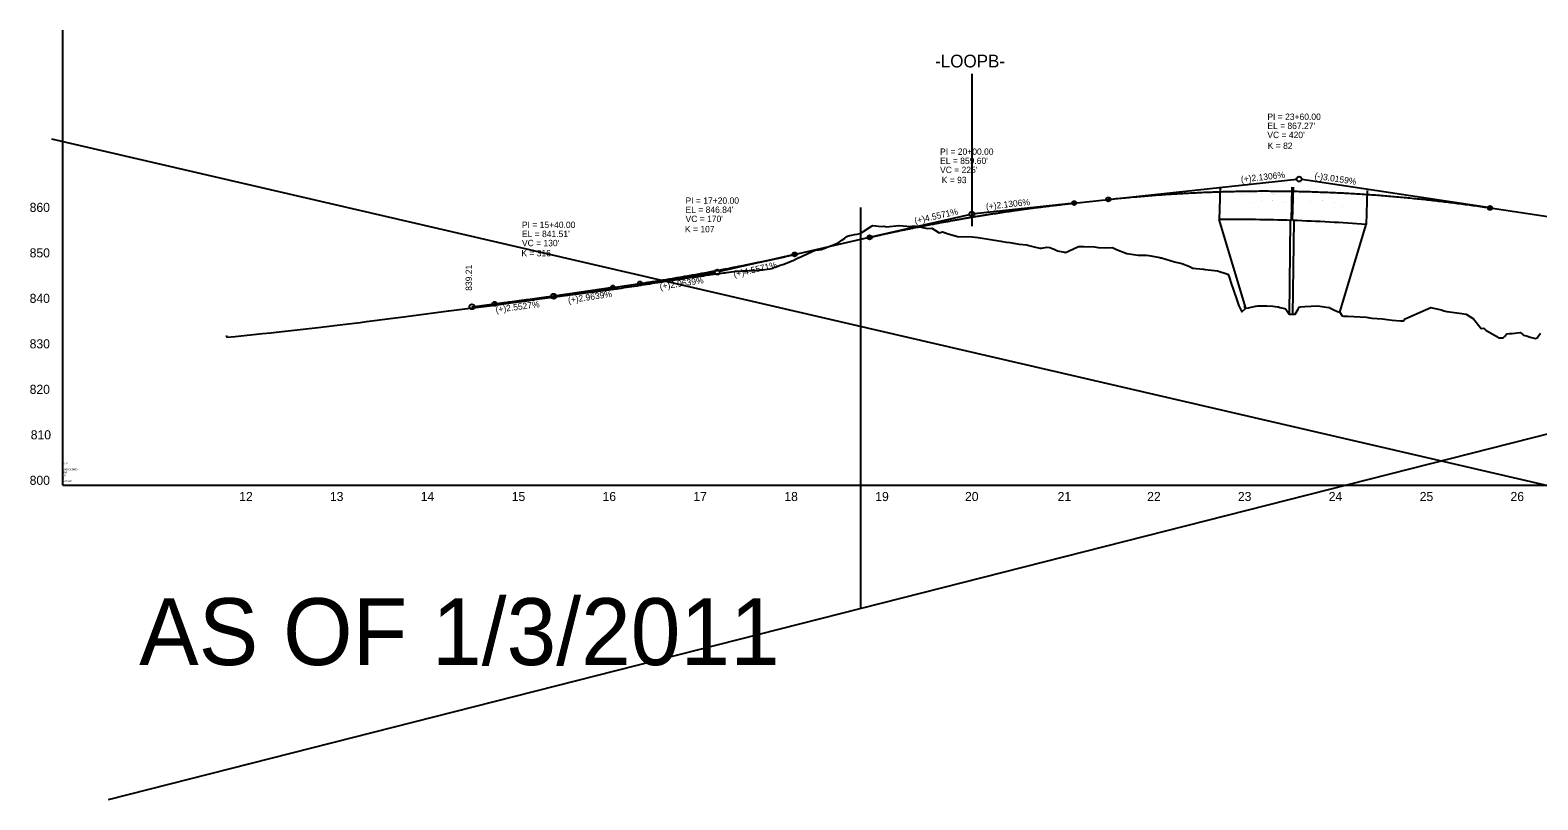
# Model space of a CAD drawing. Extents: x 570622 to 580296, y -55533 to -48575.
# Drawn here: x 573623 to 575281, y -49421 to -48575 of the extents above; entities that cross this region are included whole.
import ezdxf

# ---------------------------------------------------------------- set-up
doc = ezdxf.new("R2010")
doc.units = 0
for name, color, linetype in [('Default', 7, 'Continuous'), ('Exist Profile Cell', 7, 'Continuous'), ('Exist Vertical Profile Ground Line', 7, 'Continuous'), ('Exist Vertical Profile Horizontal Axis Label Major', 7, 'Continuous'), ('Exist Vertical Profile Vertical Axis Label', 7, 'Continuous'), ('Prop Vertical Profile Curve Label', 7, 'Continuous'), ('Prop Vertical Profile Grade', 7, 'Continuous'), ('Prop Vertical Profile Grade Label', 7, 'Continuous'), ('Prop VPI Label', 7, 'Continuous')]:
    doc.layers.add(name, color=color, linetype=linetype)

msp = doc.modelspace()

# ---------------------------------------------------------------- linework, layer by layer
at = {"layer": 'Default'}
for p, q in [((574658.6, -48623.1), (574658.6, -48790.2)), ((574931.8, -48748.4), (574930.7, -48783.1)), ((574955.7, -48754.4), (574955.7, -48754.4)), ((574957.2, -48756), (574957.2, -48756)), ((574957.2, -48756), (574957.2, -48756)), ((574963.9, -48752.7), (574963.9, -48752.7)), ((574965.4, -48754.3), (574965.4, -48754.3)), ((574965.4, -48754.3), (574965.4, -48754.3)), ((574975.6, -48752.4), (574975.6, -48752.4)), ((574977.1, -48754), (574977.1, -48754)), ((574977.2, -48754), (574977.2, -48754)), ((574987.3, -48753.5), (574987.3, -48753.5)), ((574988.8, -48755.1), (574988.8, -48755.1)), ((574988.8, -48755.1), (574988.8, -48755.1)), ((574989.9, -48754.3), (574989.9, -48754.3)), ((574991.4, -48755.9), (574991.4, -48755.9)), ((574991.4, -48755.9), (574991.4, -48755.9)), ((575010.1, -48784), (575010.9, -48747.5)), ((575011.4, -48784.1), (575012.3, -48747.5)), ((575017.7, -48752.8), (575017.7, -48752.8)), ((575019.1, -48754.5), (575019.1, -48754.5)), ((575019.1, -48754.5), (575019.1, -48754.5)), ((575030.9, -48752.1), (575030.9, -48752.1)), ((575031.7, -48752.5), (575031.7, -48752.5)), ((575032.8, -48753.7), (575032.8, -48753.7)), ((575044.2, -48754.1), (575044.2, -48754.1)), ((575045.7, -48755.8), (575045.7, -48755.8)), ((575045.7, -48755.8), (575045.7, -48755.8)), ((575052, -48758.6), (575052, -48758.6)), ((575054, -48760.2), (575054, -48760.2)), ((575054, -48760.2), (575054, -48760.2)), ((575093.4, -48751.1), (575092.2, -48788.4)), ((574536.6, -49210), (574536.6, -48769.9)), ((574968.9, -48764.8), (574968.9, -48764.8)), ((574968.9, -48764.8), (574968.9, -48764.8)), ((574977.3, -48762.7), (574977.3, -48762.7)), ((574977.3, -48762.7), (574977.3, -48762.7)), ((574989, -48762.2), (574989, -48762.2)), ((574989.1, -48762.2), (574989.1, -48762.2)), ((575000.7, -48763.3), (575000.7, -48763.3)), ((575000.7, -48763.3), (575000.7, -48763.3)), ((575003.4, -48764.1), (575003.4, -48764.1)), ((575003.4, -48764.1), (575003.4, -48764.1)), ((575031, -48762.9), (575031, -48762.9)), ((575031, -48762.9), (575031, -48762.9)), ((575044.3, -48762.2), (575044.3, -48762.2)), ((575044.6, -48762.2), (575044.6, -48762.2)), ((575057.6, -48764.1), (575057.6, -48764.1)), ((575057.6, -48764.1), (575057.6, -48764.1)), ((575066.1, -48768.4), (575066.1, -48768.4)), ((575066.1, -48768.4), (575066.1, -48768.4)), ((574959.9, -48880.6), (574930.7, -48783.1)), ((575008, -48887.7), (575009.2, -48784.1)), ((575011.8, -48887.7), (575013, -48784.1)), ((575063.3, -48884.9), (575092.2, -48788.4)), ((574958.9, -48880.6), (574958.9, -48877.3)), ((574959.9, -48880.6), (574958.9, -48880.6))]:
    msp.add_line(p, q, dxfattribs=at)
for start, end in [(88.1608, 90.5075), (85.7299, 88.1202)]:
    msp.add_arc((574947.9, -50721.6), 1938.5, start, end, dxfattribs=at)
at = {"layer": 'Exist Profile Cell'}
for p, q in [((573658.6, -49075), (573658.6, -48575)), ((576607.2, -48684.9), (573708.6, -49420.9)), ((573646, -48694.4), (576748.4, -49412.6)), ((573658.6, -49075), (576254.8, -49075)), ((573658.6, -49075), (573658.6, -49075))]:
    msp.add_line(p, q, dxfattribs=at)
at = {"layer": 'Exist Vertical Profile Ground Line'}
for points in [[(574354.9, -48846), (574356.9, -48845.7), (574357.7, -48845.6), (574360.5, -48845.2), (574363.3, -48844.8), (574366.1, -48844.3), (574368.9, -48843.9), (574369.5, -48843.9), (574371.8, -48843.5), (574374.6, -48843.1), (574377.4, -48842.7), (574377.9, -48842.6), (574380.2, -48842.3), (574383, -48842), (574385.8, -48841.6), (574387.3, -48841.5), (574388.7, -48841.3), (574391.5, -48840.9), (574393.9, -48840.6), (574394.3, -48840.5), (574397.1, -48840.1), (574398.8, -48839.9), (574399.9, -48839.8), (574402.8, -48839.7), (574405.6, -48839.6), (574408.4, -48839.5), (574411.2, -48839.3), (574414, -48839.2), (574416.8, -48839.2), (574419.7, -48839.1), (574420, -48839.1), (574422.5, -48838.8), (574425.3, -48838.5), (574428.1, -48838.2), (574430.9, -48837.9), (574433.7, -48837.7), (574436.7, -48837.4), (574439.9, -48836.4), (574440.2, -48836.2), (574440.9, -48835.9), (574442.2, -48835.4), (574445, -48834.4), (574447.8, -48833.4), (574450.6, -48832.4), (574453.5, -48831.3), (574456.3, -48830.2), (574459.1, -48829.2), (574460.6, -48828.6), (574461.9, -48828), (574464.7, -48826.7), (574467.5, -48825.3), (574470.4, -48824), (574471.8, -48823.3), (574473.2, -48822.7), (574476, -48821.4), (574478.8, -48820.1), (574481.6, -48818.8), (574484.4, -48817.5), (574486.5, -48816.6), (574487.3, -48816.5), (574490.1, -48816.4), (574492.9, -48816.1), (574495.7, -48815), (574498.5, -48813.9), (574501.3, -48812.8), (574504.2, -48811.7), (574504.6, -48811.5), (574507, -48810.5), (574509.8, -48809.4), (574511.2, -48808.9), (574512.6, -48807.9), (574515.4, -48805.8), (574518.3, -48803.8), (574521.1, -48801.8), (574521.7, -48801.3), (574522.8, -48800.9), (574523.9, -48800.7), (574526.7, -48800.1), (574529.5, -48799.6), (574532.3, -48799), (574535.7, -48798.3), (574548.8, -48789.9), (574549.5, -48789.8), (574559.3, -48790.7), (574561.6, -48790.5), (574564.6, -48791), (574578.3, -48789.8), (574578.7, -48789.7), (574591.3, -48790.7), (574592.9, -48790.5), (574597.4, -48790.3), (574609.8, -48793), (574614.7, -48792.5), (574622.7, -48797.6), (574626.1, -48796.6), (574629.7, -48797.6), (574631.4, -48798.5), (574642.6, -48801.9), (574658.8, -48802.1), (574665.6, -48802.7), (574678.9, -48805)], [(574678.9, -48805), (574690.6, -48806.7), (574692.4, -48807.3), (574696.2, -48808), (574700.2, -48808.5), (574710.7, -48810.2), (574719, -48810.8), (574721.2, -48811.7), (574727.1, -48813.2), (574733.2, -48814.6), (574735, -48814.7), (574741.1, -48813.5), (574744.2, -48813.8), (574750, -48816.2), (574752.7, -48817.6), (574760.4, -48819.1), (574761.4, -48819.2), (574765.6, -48817.4), (574775.9, -48812.8), (574780.9, -48812.6), (574781.9, -48812.6), (574793.6, -48813.1), (574797.6, -48814), (574805.6, -48814.1), (574813.2, -48814), (574817.7, -48815.9), (574828.9, -48820.3), (574841.4, -48822.1), (574850.3, -48822.1), (574853.1, -48822.6), (574863.4, -48824.4), (574865.4, -48824.8), (574866, -48825), (574867.1, -48825.3), (574881.6, -48829.5), (574889.4, -48831.4), (574897.3, -48834.4), (574901.6, -48836.5), (574912.9, -48837.7), (574913.6, -48837.8), (574915.3, -48838), (574925.5, -48839), (574928.6, -48839.4), (574939, -48842.7), (574940.3, -48843.1), (574941.3, -48845.1), (574943, -48851.3), (574950.1, -48871.4), (574952.1, -48878), (574955.5, -48884.5), (574959.9, -48880.6), (574963, -48880.1), (574970.4, -48878.4), (574971.3, -48878.2), (574973.2, -48878.1), (574983.2, -48877.8), (574989.8, -48878.4), (574994.7, -48878.9), (574995.8, -48879.2), (574997.5, -48879.7), (575002.8, -48880.9), (575003.7, -48881.1), (575004.1, -48881.6), (575007.6, -48887), (575010.1, -48887.1), (575014.1, -48887.2), (575017.4, -48881.5), (575018.6, -48879.4), (575020.1, -48879.1), (575025, -48878.5), (575031.7, -48878.2), (575038.6, -48877.9), (575051.1, -48879.7), (575051.8, -48879.8), (575052.5, -48880.2), (575057.4, -48882.6), (575059.9, -48883.9), (575060.5, -48884.1), (575063.3, -48884.9), (575066, -48889), (575067.2, -48889.4), (575072, -48889.2), (575078.8, -48889.6), (575092.4, -48890.5), (575098.6, -48891.4), (575110.1, -48892.2), (575115.3, -48892.8), (575120.9, -48893.7), (575130, -48894.3), (575133.3, -48894.4), (575134.7, -48892.2), (575135.9, -48892), (575157.7, -48882.5), (575163.6, -48879.8), (575166.3, -48880.5), (575175.2, -48882.2), (575177.9, -48883.5), (575179.3, -48883.8), (575181, -48884.1), (575194.9, -48886.1), (575202.4, -48887)], [(573838.2, -48910.7), (573839, -48912.4), (573848.2, -48911.5), (573878.1, -48908.5), (573887.5, -48907.6), (573893.1, -48907), (573923.1, -48903.6), (573939.5, -48901.8), (573969.4, -48898.2), (573985.8, -48896.2), (573992.6, -48895.3), (574015.8, -48892.4), (574033.5, -48890.1), (574058.3, -48886.8), (574082.7, -48883.5), (574083.2, -48883.4), (574106.7, -48880.4), (574107, -48880.4), (574130.8, -48877.4), (574154, -48874.4), (574168.9, -48872.3), (574171.7, -48871.9), (574174.6, -48871.5), (574176.7, -48871.2), (574177.4, -48871.1), (574180.2, -48870.7), (574183, -48870.4), (574185.8, -48870), (574188.7, -48869.6), (574191.5, -48869.2), (574194.3, -48868.9), (574197.1, -48868.5), (574199.9, -48868.1), (574202.7, -48867.8), (574205.6, -48867.4), (574206, -48867.3), (574208.4, -48867), (574211.2, -48866.7), (574214, -48866.3), (574216.8, -48865.9), (574219.6, -48865.6), (574222.5, -48865.2), (574223, -48865.2), (574225.3, -48864.8), (574228.1, -48864.5), (574230.9, -48864.1), (574233.7, -48863.7), (574236.5, -48863.4), (574239.4, -48863), (574242.2, -48862.6), (574243.6, -48862.4), (574245, -48862.3), (574245.9, -48862.2), (574247.8, -48861.9), (574250.6, -48861.5), (574253.4, -48861.1), (574256.3, -48860.7), (574259.1, -48860.3), (574261.9, -48860), (574264.4, -48859.6), (574264.7, -48859.6), (574267.5, -48859.2), (574268.9, -48859), (574270.3, -48858.8), (574273.2, -48858.4), (574276, -48857.9), (574278.8, -48857.5), (574281.6, -48857.1), (574284.1, -48856.7), (574284.4, -48856.6), (574287.2, -48856.2), (574290.1, -48855.8), (574290.5, -48855.8), (574292.9, -48855.4), (574295.7, -48855), (574298.5, -48854.5), (574301.3, -48854.1), (574303.1, -48853.8), (574304.2, -48853.6), (574307, -48853.2), (574309.8, -48852.8), (574312.2, -48852.4), (574312.6, -48852.3), (574315.4, -48851.9), (574318.2, -48851.5), (574321.1, -48851), (574322, -48850.9), (574323.9, -48850.6), (574326.7, -48850.2), (574329.5, -48849.8), (574332.3, -48849.3), (574334.6, -48849), (574335.1, -48848.9), (574338, -48848.5), (574340.8, -48848.1), (574343.6, -48847.6), (574346.4, -48847.2), (574349.2, -48846.8), (574352, -48846.4), (574353.6, -48846.1), (574354.9, -48846)], [(575202.4, -48887), (575210.5, -48892.2), (575218.9, -48902.8), (575221.7, -48902.5), (575224.1, -48904.7), (575235.9, -48911.8), (575238, -48913), (575238.8, -48913), (575241.6, -48913.1), (575242.9, -48913.2), (575244.4, -48911.5), (575247.2, -48908.6), (575250.1, -48908.4), (575252.9, -48908.2), (575255.7, -48907.9), (575258.5, -48907.7), (575261.4, -48907.4), (575261.8, -48907.4), (575264.2, -48909.2), (575265.4, -48910.1), (575267, -48910.6), (575269.8, -48911.4), (575272.7, -48912.2), (575275.5, -48913), (575278.5, -48913.8), (575280.5, -48913), (575281.1, -48912.1), (575284, -48908)]]:
    msp.add_lwpolyline(points, dxfattribs=at)
at = {"layer": 'Prop Vertical Profile Curve Label'}
for centre in [(574808.6, -48761), (574771.1, -48765), (575228.6, -48770.3), (574546.1, -48802.6), (574463.6, -48821.4), (574263.6, -48857.8), (574293.6, -48853.4), (574133.6, -48875.7)]:
    msp.add_circle(centre, 2.25, dxfattribs=at)
at = {"layer": 'Prop Vertical Profile Grade'}
for p, q in [((574771.1, -48765), (574808.6, -48761)), ((575228.6, -48770.3), (575348.6, -48788.4)), ((574463.6, -48821.4), (574546.1, -48802.6)), ((574263.6, -48857.8), (574293.6, -48853.4)), ((574108.6, -48878.9), (574133.6, -48875.7))]:
    msp.add_line(p, q, dxfattribs=at)
for points in [[(574808.6, -48761), (574817, -48760.1), (574825.4, -48759.3), (574833.8, -48758.5), (574842.2, -48757.8), (574850.6, -48757.1), (574859, -48756.4), (574867.4, -48755.8), (574875.8, -48755.2), (574884.2, -48754.7), (574892.6, -48754.2), (574901, -48753.8), (574909.4, -48753.4), (574917.8, -48753), (574926.2, -48752.7), (574934.6, -48752.4), (574943, -48752.2), (574951.4, -48752), (574959.8, -48751.9), (574968.2, -48751.8), (574976.6, -48751.7), (574985, -48751.7), (574993.4, -48751.8), (575001.8, -48751.8), (575010.2, -48752), (575018.6, -48752.1), (575027, -48752.3), (575035.4, -48752.6), (575043.8, -48752.9), (575052.2, -48753.2), (575060.6, -48753.6), (575069, -48754), (575077.4, -48754.5), (575085.8, -48755), (575094.2, -48755.6), (575102.6, -48756.1), (575111, -48756.8), (575119.4, -48757.5), (575127.8, -48758.2), (575136.2, -48759), (575144.6, -48759.8), (575153, -48760.6), (575161.4, -48761.5), (575169.8, -48762.5), (575178.2, -48763.5), (575186.6, -48764.5), (575195, -48765.6), (575203.4, -48766.7), (575211.8, -48767.8), (575220.2, -48769), (575228.6, -48770.3)], [(574546.1, -48802.6), (574550.6, -48801.6), (574555.1, -48800.6), (574559.6, -48799.6), (574564.1, -48798.6), (574568.6, -48797.6), (574573.1, -48796.6), (574577.6, -48795.7), (574582.1, -48794.7), (574586.6, -48793.8), (574591.1, -48792.9), (574595.6, -48792), (574600.1, -48791.1), (574604.6, -48790.2), (574609.1, -48789.3), (574613.6, -48788.4), (574618.1, -48787.6), (574622.6, -48786.7), (574627.1, -48785.9), (574631.6, -48785.1), (574636.1, -48784.3), (574640.6, -48783.5), (574645.1, -48782.7), (574649.6, -48781.9), (574654.1, -48781.1), (574658.6, -48780.4), (574663.1, -48779.6), (574667.6, -48778.9), (574672.1, -48778.2), (574676.6, -48777.5), (574681.1, -48776.8), (574685.6, -48776.1), (574690.1, -48775.4), (574694.6, -48774.7), (574699.1, -48774.1), (574703.6, -48773.4), (574708.1, -48772.8), (574712.6, -48772.1), (574717.1, -48771.5), (574721.6, -48770.9), (574726.1, -48770.3), (574730.6, -48769.7), (574735.1, -48769.2), (574739.6, -48768.6), (574744.1, -48768.1), (574748.6, -48767.5), (574753.1, -48767), (574757.6, -48766.5), (574762.1, -48766), (574766.6, -48765.5), (574771.1, -48765)], [(574293.6, -48853.4), (574297, -48852.9), (574300.4, -48852.3), (574303.8, -48851.8), (574307.2, -48851.3), (574310.6, -48850.8), (574314, -48850.2), (574317.4, -48849.7), (574320.8, -48849.2), (574324.2, -48848.6), (574327.6, -48848.1), (574331, -48847.5), (574334.4, -48846.9), (574337.8, -48846.4), (574341.2, -48845.8), (574344.6, -48845.2), (574348, -48844.6), (574351.4, -48844), (574354.8, -48843.4), (574358.2, -48842.8), (574361.6, -48842.2), (574365, -48841.6), (574368.4, -48841), (574371.8, -48840.3), (574375.2, -48839.7), (574378.6, -48839.1), (574382, -48838.4), (574385.4, -48837.8), (574388.8, -48837.1), (574392.2, -48836.5), (574395.6, -48835.8), (574399, -48835.1), (574402.4, -48834.5), (574405.8, -48833.8), (574409.2, -48833.1), (574412.6, -48832.4), (574416, -48831.7), (574419.4, -48831), (574422.8, -48830.3), (574426.2, -48829.6), (574429.6, -48828.9), (574433, -48828.2), (574436.4, -48827.4), (574439.8, -48826.7), (574443.2, -48826), (574446.6, -48825.2), (574450, -48824.5), (574453.4, -48823.7), (574456.8, -48822.9), (574460.2, -48822.2), (574463.6, -48821.4)], [(574133.6, -48875.7), (574136.2, -48875.4), (574138.8, -48875.1), (574141.4, -48874.7), (574144, -48874.4), (574146.6, -48874.1), (574149.2, -48873.7), (574151.8, -48873.4), (574154.4, -48873), (574157, -48872.7), (574159.6, -48872.4), (574162.2, -48872), (574164.8, -48871.7), (574167.4, -48871.3), (574170, -48871), (574172.6, -48870.6), (574175.2, -48870.3), (574177.8, -48869.9), (574180.4, -48869.6), (574183, -48869.2), (574185.6, -48868.9), (574188.2, -48868.5), (574190.8, -48868.2), (574193.4, -48867.8), (574196, -48867.5), (574198.6, -48867.1), (574201.2, -48866.7), (574203.8, -48866.4), (574206.4, -48866), (574209, -48865.7), (574211.6, -48865.3), (574214.2, -48864.9), (574216.8, -48864.6), (574219.4, -48864.2), (574222, -48863.8), (574224.6, -48863.5), (574227.2, -48863.1), (574229.8, -48862.7), (574232.4, -48862.4), (574235, -48862), (574237.6, -48861.6), (574240.2, -48861.2), (574242.8, -48860.9), (574245.4, -48860.5), (574248, -48860.1), (574250.6, -48859.7), (574253.2, -48859.3), (574255.8, -48859), (574258.4, -48858.6), (574261, -48858.2), (574263.6, -48857.8)]]:
    msp.add_spline(points, degree=3, dxfattribs=at)
at = {"layer": 'Prop VPI Label'}
for p, q in [((574808.6, -48761), (575015.9, -48738.9)), ((575228.6, -48770.3), (575021.4, -48739)), ((574771.1, -48765), (574661.4, -48776.7)), ((574546.1, -48802.6), (574656, -48777.6)), ((574463.6, -48821.4), (574381.3, -48840.2)), ((574293.6, -48853.4), (574375.9, -48841.2)), ((574263.6, -48857.8), (574201.4, -48867)), ((574133.6, -48875.7), (574195.9, -48867.8))]:
    msp.add_line(p, q, dxfattribs=at)
for centre in [(575018.6, -48738.6), (574658.6, -48777), (574378.6, -48840.8), (574108.6, -48878.9), (574108.6, -48878.9), (574198.6, -48867.4)]:
    msp.add_circle(centre, 2.75, dxfattribs=at)

# ---------------------------------------------------------------- texts
at = {"layer": 'Default'}
msp.add_text('AS OF 1/3/2011', height=73.5, dxfattribs=at).set_placement((573742.5, -49272.8))
at = {"layer": 'Exist Profile Cell'}
for s, height, p in [('-LOOPB-', 14, (574618.1, -48615.9)), ('1000.000000', 2, (573658.6, -49058.7)), ('RDY', 2, (573658.6, -49052.2)), ('L', 2, (573658.6, -49055.5)), ('800', 2, (573658.6, -49062)), ('10', 2, (573658.6, -49065.2)), ('2', 2, (573658.6, -49068.5)), ('NOGAP', 2, (573658.6, -49071.7))]:
    msp.add_text(s, height=height, dxfattribs=at).set_placement(p)
at = {"layer": 'Exist Vertical Profile Horizontal Axis Label Major'}
for s, p in [('12', (573852.6, -49092.5)), ('13', (573952.4, -49092.5)), ('14', (574052.3, -49092.5)), ('15', (574152.4, -49092.5)), ('16', (574252.3, -49092.5)), ('17', (574352.2, -49092.5)), ('18', (574452.3, -49092.5)), ('19', (574552.3, -49092.5)), ('20', (574651, -49092.5)), ('21', (574752.9, -49092.5)), ('22', (574851.4, -49092.5)), ('23', (574951.2, -49092.5)), ('24', (575051.1, -49092.5)), ('25', (575151.2, -49092.5)), ('26', (575251.1, -49092.5))]:
    msp.add_text(s, height=10, dxfattribs=at).set_placement(p)
at = {"layer": 'Exist Vertical Profile Vertical Axis Label'}
for s, p in [('860', (573622.1, -48774.7)), ('850', (573622.1, -48824.7)), ('840', (573622.1, -48874.7)), ('830', (573622.1, -48924.7)), ('820', (573622.1, -48974.7)), ('810', (573623.3, -49024.7)), ('800', (573622.1, -49074.7))]:
    msp.add_text(s, height=10, dxfattribs=at).set_placement(p)
at = {"layer": 'Prop Vertical Profile Curve Label'}
for s, p in [("VC = 420'", (574983.6, -48693.6)), ('K = 82', (574984, -48705.5)), ("VC = 225'", (574623.6, -48732)), ('K = 93', (574625.4, -48743.1)), ("VC = 170'", (574343.6, -48785.8)), ('K = 107', (574343, -48797.1)), ("VC = 130'", (574163.6, -48812.4)), ('K = 316', (574163, -48823.5))]:
    msp.add_text(s, height=7, dxfattribs=at).set_placement(p)
at = {"layer": 'Prop Vertical Profile Grade Label'}
for s, rotation, p in [('(+)2.1306%', 6.0807, (574954.9, -48742.4)), ('(-)3.0159%', 351.4247, (575035.2, -48738.1)), ('(+)4.5571%', 12.8361, (574596.3, -48788.1)), ('(+)2.1306%', 6.0807, (574674.4, -48772.3)), ('(+)4.5571%', 12.8361, (574397.2, -48846.8)), ('(+)2.9639%', 8.4296, (574315.7, -48860.2)), ('(+)2.5527%', 7.2735, (574135.1, -48885.6)), ('(+)2.9639%', 8.4296, (574214.8, -48875.2))]:
    msp.add_text(s, height=7, rotation=rotation, dxfattribs=at).set_placement(p)
at = {"layer": 'Prop VPI Label'}
for s, p in [('PI = 23+60.00', (574983.6, -48673.6)), ("EL = 867.27'", (574983.6, -48683.6)), ('PI = 20+00.00', (574623.6, -48712)), ("EL = 859.60'", (574623.6, -48722)), ('PI = 17+20.00', (574343.6, -48765.8)), ("EL = 846.84'", (574343.6, -48775.8)), ('PI = 15+40.00', (574163.6, -48792.4)), ("EL = 841.51'", (574163.6, -48802.4))]:
    msp.add_text(s, height=7, dxfattribs=at).set_placement(p)
msp.add_text('839.21', height=7, rotation=90, dxfattribs=at).set_placement((574108.6, -48861.4))
msp.add_text('839.21', height=7, rotation=90, dxfattribs=at).set_placement((574108.6, -48861.4))

doc.saveas('drawing.dxf')
